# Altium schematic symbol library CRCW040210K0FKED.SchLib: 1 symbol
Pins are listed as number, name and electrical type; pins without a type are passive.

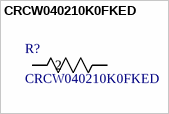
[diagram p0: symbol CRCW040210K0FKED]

## CRCW040210K0FKED
designator R?
D10/CRCW0402 100 10K 1% ET7 e3; Manufacturer_Name: Vishay
footprint RES_CRCW_0402
pins: 1, 2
